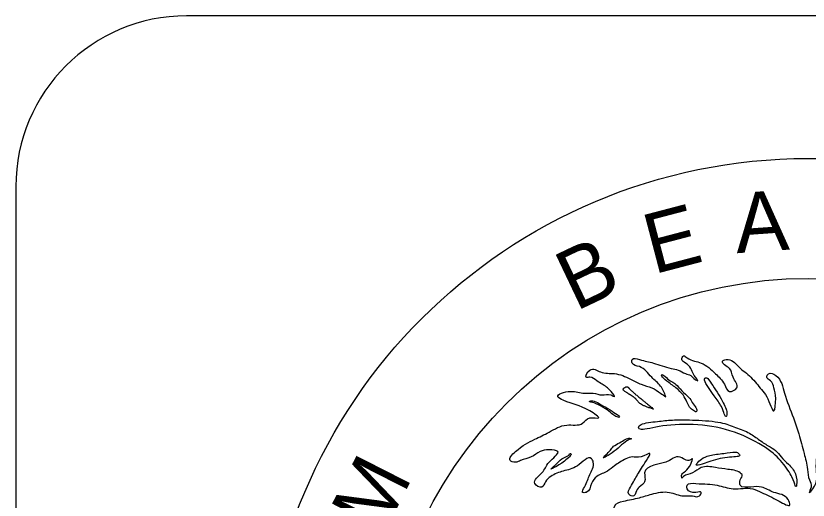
# Model space of a CAD drawing. Extents: x -1.6 to 33.4, y -12.7 to 10.9.
# Drawn here: x 26.6293 to 27.0389, y -12.2245 to -11.9742 of the extents above; entities that cross this region are included whole.
import ezdxf

# ---------------------------------------------------------------- set-up
doc = ezdxf.new("R2010")
doc.units = 0
doc.layers.add('Default', color=7, linetype='Continuous')

msp = doc.modelspace()

# ---------------------------------------------------------------- linework, layer by layer
at = {"layer": 'Default'}
for p, q in [((29.14345, -11.9742), (26.71752, -11.9742)), ((26.6293, -12.06242), (26.6293, -12.58734))]:
    msp.add_line(p, q, dxfattribs=at)
for radius in [0.28241, 0.22041]:
    msp.add_circle((27.03883, -12.33032), radius, dxfattribs=at)
msp.add_ellipse((26.71752, -12.06242), major_axis=(0, 0.08822), ratio=0.999927, start_param=0, end_param=1.570796, dxfattribs=at)
for points in [[(26.96534, -12.17104), (26.9626, -12.16553), (26.95802, -12.16096), (26.95162, -12.15548), (26.94795, -12.15363), (26.94795, -12.1518), (26.95162, -12.15182), (26.95893, -12.15364), (26.96809, -12.15638), (26.97175, -12.1573), (26.97543, -12.15912), (26.97817, -12.16005), (26.97908, -12.16097), (26.98182, -12.16279), (26.98, -12.16004), (26.97817, -12.15639), (26.97541, -12.15363), (26.97359, -12.15181), (26.97451, -12.14999), (26.97634, -12.15089), (26.98365, -12.15365), (26.99099, -12.15913), (26.99556, -12.16462), (26.99831, -12.16828), (27.00196, -12.16646), (27.00014, -12.16096), (26.99831, -12.15638), (26.99557, -12.15455), (26.99464, -12.15272), (26.99647, -12.15181), (27.00289, -12.15546), (27.00929, -12.16096), (27.01477, -12.16737), (27.01753, -12.17103), (27.0212, -12.17835), (27.0221, -12.17194), (27.02119, -12.16645), (27.01935, -12.1628), (27.01753, -12.16096), (27.01845, -12.15913), (27.02211, -12.16004), (27.02669, -12.1692), (27.03127, -12.18201), (27.034, -12.19027), (27.03676, -12.20033), (27.03858, -12.20857), (27.03951, -12.21405), (27.04041, -12.21772), (27.0395, -12.22046), (27.04134, -12.21864), (27.04315, -12.20857), (27.04499, -12.19483), (27.04773, -12.18569), (27.04957, -12.1756), (27.05048, -12.16737), (27.05233, -12.15914), (27.05415, -12.1518), (27.05323, -12.14358), (27.05322, -12.13992), (27.05598, -12.13716), (27.05598, -12.13808), (27.05782, -12.14175), (27.05874, -12.14997), (27.05964, -12.15638), (27.06146, -12.15822), (27.06238, -12.15365), (27.05964, -12.14357), (27.05964, -12.13899), (27.06239, -12.13717), (27.0633, -12.13899), (27.0633, -12.14265), (27.06513, -12.14357), (27.06422, -12.13716), (27.06605, -12.13259), (27.06513, -12.12618), (27.06422, -12.12343), (27.06696, -12.12161), (27.0697, -12.12618), (27.07338, -12.13624), (27.07611, -12.1445), (27.07886, -12.14815), (27.07887, -12.15181), (27.07888, -12.1454), (27.07888, -12.13625), (27.07888, -12.12709), (27.07796, -12.12251), (27.07704, -12.11335)], [(26.97358, -12.21315), (26.97359, -12.21132), (26.97543, -12.20947), (26.97817, -12.20582), (26.97908, -12.20308), (26.97724, -12.20399), (26.9745, -12.20308), (26.97084, -12.20215), (26.96717, -12.20398), (26.95437, -12.2104), (26.95437, -12.21497), (26.95161, -12.21773), (26.94979, -12.22047), (26.94886, -12.22229), (26.94612, -12.22139), (26.94703, -12.21773), (26.9507, -12.21132), (26.95527, -12.20399), (26.95712, -12.20032), (26.95253, -12.20215), (26.94796, -12.20215), (26.94156, -12.20491), (26.9388, -12.20673), (26.93515, -12.20948), (26.92964, -12.21222), (26.9269, -12.21589), (26.92415, -12.22048), (26.92232, -12.22047), (26.92323, -12.21773), (26.92598, -12.21131), (26.92782, -12.20491), (26.92689, -12.20307), (26.91958, -12.20675), (26.91226, -12.20948), (26.90584, -12.21224), (26.9031, -12.21497), (26.90126, -12.21773), (26.8976, -12.21588), (26.90127, -12.21041), (26.90494, -12.20491), (26.9095, -12.19942), (26.90492, -12.1985), (26.90034, -12.19942), (26.89577, -12.20216), (26.89027, -12.20399), (26.88754, -12.20491), (26.88478, -12.20399), (26.88753, -12.19942), (26.8976, -12.193), (26.90492, -12.18935), (26.91407, -12.18568), (26.92232, -12.18476), (26.92599, -12.18201), (26.93057, -12.18201), (26.92599, -12.17835), (26.91226, -12.17286), (26.9095, -12.17104), (26.91592, -12.16828), (26.92324, -12.16921), (26.92782, -12.16921), (26.93239, -12.17012), (26.93697, -12.17012), (26.9388, -12.17102), (26.93698, -12.16829), (26.9324, -12.16463), (26.92964, -12.16278), (26.92598, -12.16096), (26.92415, -12.16097), (26.92598, -12.1573), (26.93147, -12.15822), (26.93881, -12.15912), (26.94703, -12.16189), (26.95254, -12.16462), (26.95802, -12.16645), (26.96261, -12.1692), (26.96534, -12.17104)], [(26.90951, -12.30195), (26.90951, -12.29829), (26.91042, -12.29463), (26.91133, -12.29003), (26.91134, -12.28454), (26.91317, -12.28364), (26.91317, -12.28455), (26.91774, -12.2818), (26.91959, -12.28273), (26.91957, -12.28548), (26.92048, -12.28637), (26.9214, -12.28546), (26.92141, -12.28455), (26.9269, -12.27082), (26.92598, -12.27173), (26.92324, -12.27449), (26.92048, -12.27722), (26.91775, -12.27997), (26.91591, -12.2818), (26.91316, -12.2818), (26.91316, -12.27723), (26.91409, -12.27357), (26.91408, -12.27082), (26.91042, -12.27174), (26.90676, -12.27447), (26.9031, -12.27539), (26.89945, -12.27814), (26.89853, -12.27814), (26.89578, -12.27906), (26.89303, -12.27996), (26.8912, -12.27998), (26.89211, -12.27632), (26.89761, -12.27081), (26.90219, -12.26532), (26.90492, -12.26258), (26.90676, -12.26074), (26.9031, -12.26074), (26.89944, -12.26075), (26.89943, -12.2635), (26.89578, -12.26442), (26.89487, -12.26441), (26.89395, -12.26074), (26.90217, -12.25433), (26.91042, -12.24886), (26.91682, -12.24518), (26.91957, -12.24428), (26.92142, -12.24152), (26.91959, -12.24153), (26.91592, -12.24151), (26.91499, -12.2397), (26.91684, -12.23694), (26.92506, -12.23511), (26.93149, -12.23237), (26.93788, -12.23146), (26.94429, -12.23053), (26.94246, -12.22963), (26.9388, -12.22961), (26.93881, -12.22778), (26.94338, -12.22504), (26.95163, -12.22322), (26.95802, -12.22138), (26.96718, -12.22046), (26.97449, -12.22231), (26.97907, -12.22231), (26.98273, -12.2223), (26.98366, -12.22048), (26.98091, -12.22046), (26.97634, -12.21863), (26.97633, -12.2168), (26.98091, -12.21589), (26.99189, -12.21681), (27.00015, -12.21864), (27.01022, -12.21864), (27.01478, -12.22047), (27.02394, -12.22505), (27.02942, -12.22688), (27.02852, -12.22413), (27.02119, -12.22046), (27.01478, -12.21773), (27.00928, -12.21772), (27.00379, -12.2168), (27.00381, -12.21405), (27.00471, -12.21131), (27.0038, -12.21039), (26.99738, -12.20858), (26.99098, -12.20765), (26.98365, -12.20766), (26.97909, -12.21041), (26.9745, -12.21224), (26.97358, -12.21315)]]:
    msp.add_spline(points, degree=3, dxfattribs=at)
for points, degree in [([(26.98091, -12.17881), (26.98122, -12.17866), (26.98184, -12.17744), (26.97908, -12.1747), (26.97816, -12.17195), (26.97451, -12.16921), (26.97085, -12.16461), (26.96902, -12.16371), (26.96626, -12.16187), (26.96353, -12.15913), (26.96261, -12.16004), (26.96534, -12.1628), (26.97084, -12.16645), (26.9745, -12.17013), (26.97634, -12.17377), (26.97724, -12.17652), (26.98, -12.17835), (26.98061, -12.17896), (26.98091, -12.17881)], 3), ([(26.98625, -12.16127), (26.98579, -12.16126), (26.98457, -12.16187), (26.98732, -12.16646), (26.99007, -12.17011), (26.99463, -12.17652), (26.99555, -12.18019), (26.99648, -12.18202), (26.99739, -12.17928), (26.99465, -12.17286), (26.98732, -12.16188), (26.98671, -12.16127), (26.98625, -12.16127)], 3), ([(26.95895, -12.17744), (26.95346, -12.17286), (26.94887, -12.1692), (26.94612, -12.16646), (26.94521, -12.16554), (26.94245, -12.16738), (26.94704, -12.17013), (26.94978, -12.17195), (26.95253, -12.1756), (26.95895, -12.17744)], 2), ([(26.94109, -12.18172), (26.94155, -12.18172), (26.94154, -12.18111), (26.9388, -12.17926), (26.93421, -12.17652), (26.92965, -12.17377), (26.92691, -12.17286), (26.92507, -12.17377), (26.92782, -12.17378), (26.9333, -12.17653), (26.93697, -12.17928), (26.93879, -12.18109), (26.94063, -12.18171), (26.94109, -12.18172)], 3), ([(27.03217, -12.21696), (27.03247, -12.21772), (27.03308, -12.21772), (27.0331, -12.2104), (27.02852, -12.20582), (27.02485, -12.20217), (27.0221, -12.19849), (27.01845, -12.19666), (27.01295, -12.193), (27.00837, -12.18934), (27.00015, -12.18659), (26.99373, -12.18384), (26.97817, -12.18294), (26.9681, -12.18293), (26.96169, -12.18384), (26.9507, -12.18477), (26.9507, -12.18935), (26.96259, -12.18568), (26.98182, -12.18476), (27.00105, -12.18843), (27.01845, -12.19758), (27.02578, -12.20489), (27.03125, -12.21314), (27.03186, -12.21619), (27.03217, -12.21696)], 3), ([(26.9475, -12.19285), (26.94765, -12.1927), (26.94704, -12.1921), (26.94429, -12.193), (26.94154, -12.19484), (26.93789, -12.19667), (26.93696, -12.1985), (26.93423, -12.20123), (26.93239, -12.20308), (26.93422, -12.20215), (26.93879, -12.1994), (26.94247, -12.19576), (26.94612, -12.19301), (26.94734, -12.193), (26.9475, -12.19285)], 3), ([(26.91562, -12.20049), (26.91531, -12.20064), (26.91592, -12.20123), (26.91133, -12.20307), (26.90859, -12.20582), (26.90583, -12.20858), (26.90583, -12.20858), (26.91134, -12.20581), (26.91775, -12.20033), (26.91592, -12.20033), (26.91562, -12.20049)], 3), ([(27.00304, -12.20047), (27.00258, -12.20002), (27.00196, -12.19942), (26.99557, -12.20033), (26.98732, -12.20125), (26.98365, -12.20308), (26.98092, -12.20582), (26.98091, -12.20673), (26.98458, -12.20581), (26.99464, -12.20215), (27.00471, -12.20216), (27.0035, -12.20093), (27.00304, -12.20047)], 3)]:
    msp.add_open_spline(points, degree=degree, dxfattribs=at)

# ---------------------------------------------------------------- texts
for s, rotation, p in [('A', 3.9657, (27.00197, -12.09689)), ('E', 14.7047, (26.95893, -12.10787)), ('B', 25.4436, (26.91867, -12.1271)), ('M', 63.0299, (26.81887, -12.24337))]:
    msp.add_text(s, height=0.031, rotation=rotation, dxfattribs=at).set_placement(p)

doc.saveas('drawing.dxf')
